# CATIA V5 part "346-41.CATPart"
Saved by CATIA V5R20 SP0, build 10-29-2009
Part number: 346-41
Definition: NONE
Nomenclature: 346-41
Source: Unknown
Description: 346-41
Bounding box of the stored display mesh (mm): x 0 to 80, y -41.5 to 41.5, z -41.5 to 41.5
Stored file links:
  C:\Users\Utente\Desktop\IO LAVORO\3D X SITO CF\X SITO\3D files 346\346-41.CATPart
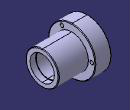
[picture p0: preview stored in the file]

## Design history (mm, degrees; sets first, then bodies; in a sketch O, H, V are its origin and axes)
Body1 "346-41" (main body)
  Solid1: solid without history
